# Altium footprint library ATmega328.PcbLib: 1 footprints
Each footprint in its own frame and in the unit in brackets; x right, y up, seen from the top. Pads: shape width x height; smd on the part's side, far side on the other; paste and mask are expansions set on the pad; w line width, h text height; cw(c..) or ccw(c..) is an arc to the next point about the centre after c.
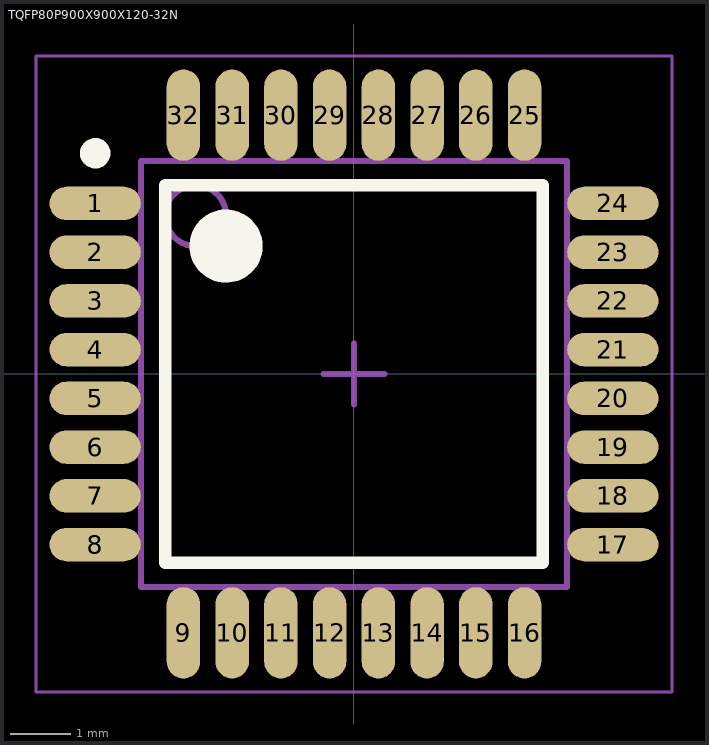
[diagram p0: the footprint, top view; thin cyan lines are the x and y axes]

## TQFP80P900X900X120-32N [mm] "TQFP, 32-Leads, Body 7.00x7.00mm, Pitch 0.80mm, IPC Medium Density"
height 1.2
pads (32):
  oval 1.5x0.55 smd: 1(-4.25,2.8) 2(-4.25,2) 3(-4.25,1.2) 4(-4.25,0.4) 5(-4.25,-0.4) 6(-4.25,-1.2) 7(-4.25,-2) 8(-4.25,-2.8) 17(4.25,-2.8) 18(4.25,-2) 19(4.25,-1.2) 20(4.25,-0.4) 21(4.25,0.4) 22(4.25,1.2) 23(4.25,2) 24(4.25,2.8)
  oval 0.55x1.5 smd: 9(-2.8,-4.25) 10(-2,-4.25) 11(-1.2,-4.25) 12(-0.4,-4.25) 13(0.4,-4.25) 14(1.2,-4.25) 15(2,-4.25) 16(2.8,-4.25) 25(2.8,4.25) 26(2,4.25) 27(1.2,4.25) 28(0.4,4.25) 29(-0.4,4.25) 30(-1.2,4.25) 31(-2,4.25) 32(-2.8,4.25)
Top Overlay:
  circle w0.6: c-2.1,2.1 r0.3
  circle w0.25: c-4.25,3.625 r0.125
  lines w0.2: -3.1,-3.1 3.1,-3.1 3.1,3.1 -3.1,3.1 -3.1,-3.1
Mechanical 13:
  circle w0.1: c-2.6,2.6 r0.5
  lines w0.1: -3.5,-3.5 3.5,-3.5 3.5,3.5 -3.5,3.5 -3.5,-3.5
Mechanical 15:
  lines w0.05: -5.225,-5.225 5.225,-5.225 5.225,5.225 -5.225,5.225 -5.225,-5.225
  lines w0.1: -0.5,0 0.5,0 ; 0,-0.5 0,0.5
3D body: height 1.2, standoff 0.25, extent -3.5,-3.5 3.5,3.5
